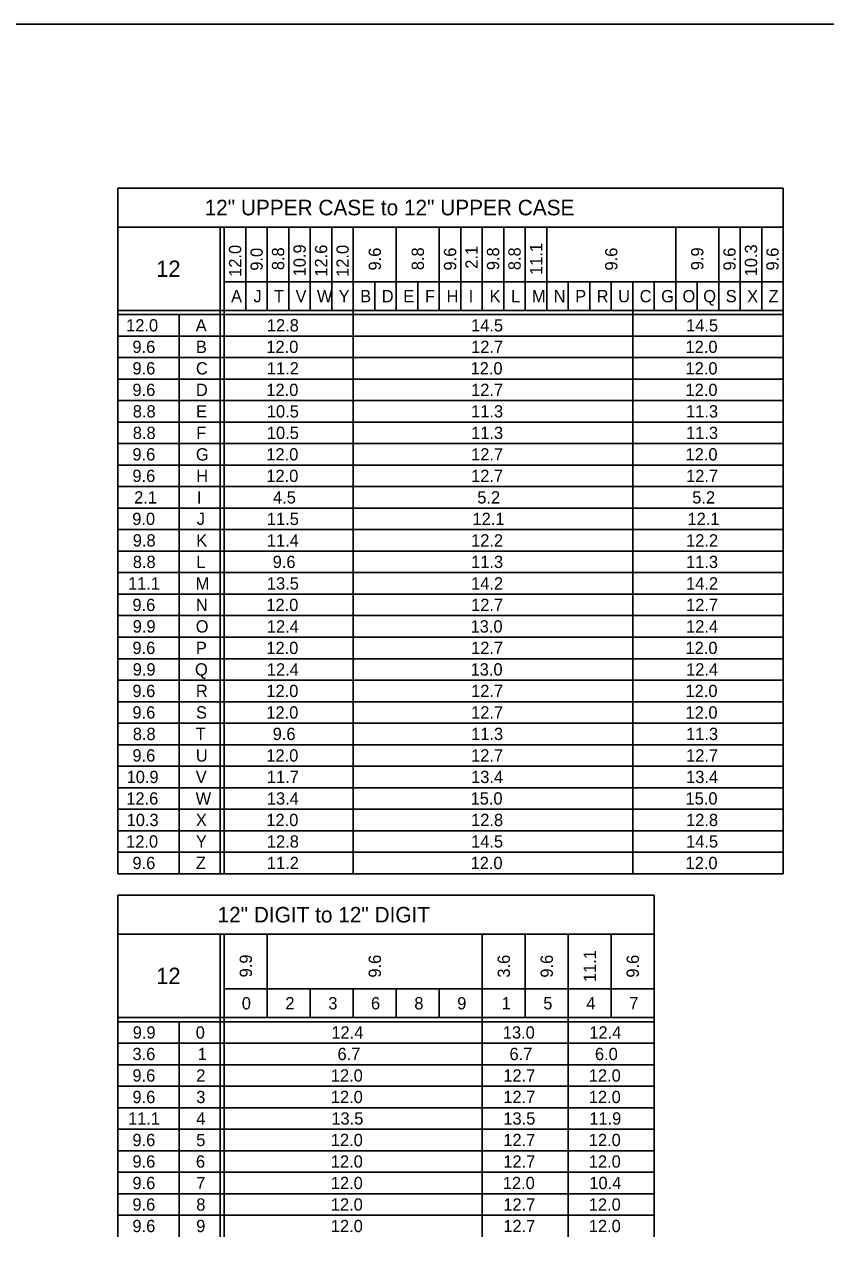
# Model space of a CAD drawing. Extents: x 637580 to 641849, y 297270 to 299646.
# Drawn here: x 640337.3 to 640533.1, y 298740.6 to 299036.6 of the extents above; entities that cross this region are included whole.
import ezdxf

# ---------------------------------------------------------------- set-up
doc = ezdxf.new("R2010")
doc.units = 0
doc.layers.add('1', color=7, linetype='Continuous')
doc.layers.add('2', color=7, linetype='Continuous')

msp = doc.modelspace()

# ---------------------------------------------------------------- linework, layer by layer
at = {"layer": '1'}
msp.add_line((640143.31, 299036.63), (640929.31, 299036.63), dxfattribs=at)
at = {"layer": '2'}
for p, q in [((640522.71, 298996.63), (640360.21, 298996.63)), ((640360.21, 298996.63), (640360.21, 298829.25)), ((640522.71, 298996.63), (640522.71, 298829.25)), ((640360.21, 298987.13), (640522.71, 298987.13)), ((640385.21, 298987.13), (640385.21, 298829.25)), ((640386.21, 298987.13), (640386.21, 298829.25)), ((640391.46, 298987.13), (640391.46, 298966.75)), ((640396.71, 298987.13), (640396.71, 298966.75)), ((640401.96, 298987.13), (640401.96, 298966.75)), ((640407.21, 298987.13), (640407.21, 298966.75)), ((640412.46, 298987.13), (640412.46, 298966.75)), ((640417.71, 298987.13), (640417.71, 298829.25)), ((640428.21, 298987.13), (640428.21, 298966.75)), ((640438.71, 298987.13), (640438.71, 298966.75)), ((640443.96, 298987.13), (640443.96, 298966.75)), ((640449.21, 298987.13), (640449.21, 298966.75)), ((640454.46, 298987.13), (640454.46, 298966.75)), ((640459.71, 298987.13), (640459.71, 298966.75)), ((640464.96, 298987.13), (640464.96, 298966.75)), ((640496.46, 298987.13), (640496.46, 298966.75)), ((640506.96, 298987.13), (640506.96, 298966.75)), ((640512.21, 298987.13), (640512.21, 298966.75)), ((640517.46, 298987.13), (640517.46, 298966.75)), ((640386.21, 298973.75), (640522.71, 298973.75)), ((640422.96, 298973.75), (640422.96, 298966.75)), ((640433.46, 298973.75), (640433.46, 298966.75)), ((640470.21, 298973.75), (640470.21, 298966.75)), ((640475.46, 298973.75), (640475.46, 298966.75)), ((640480.71, 298973.75), (640480.71, 298966.75)), ((640480.71, 298973.75), (640480.71, 298966.75)), ((640485.96, 298973.75), (640485.96, 298829.25)), ((640491.21, 298973.75), (640491.21, 298966.75)), ((640501.71, 298973.75), (640501.71, 298966.75)), ((640522.71, 298966.75), (640360.21, 298966.75)), ((640522.71, 298965.75), (640360.21, 298965.75)), ((640375.21, 298965.75), (640375.21, 298829.25)), ((640522.71, 298960.5), (640360.21, 298960.5)), ((640522.71, 298955.25), (640360.21, 298955.25)), ((640522.71, 298950), (640360.21, 298950)), ((640522.71, 298944.75), (640360.21, 298944.75)), ((640522.71, 298939.5), (640360.21, 298939.5)), ((640522.71, 298934.25), (640360.21, 298934.25)), ((640522.71, 298929), (640360.21, 298929)), ((640522.71, 298923.75), (640360.21, 298923.75)), ((640522.71, 298918.5), (640360.21, 298918.5)), ((640522.71, 298913.25), (640360.21, 298913.25)), ((640522.71, 298908), (640360.21, 298908)), ((640522.71, 298902.75), (640360.21, 298902.75)), ((640522.71, 298897.5), (640360.21, 298897.5)), ((640522.71, 298892.25), (640360.21, 298892.25)), ((640522.71, 298887), (640360.21, 298887)), ((640522.71, 298881.75), (640360.21, 298881.75)), ((640522.71, 298876.5), (640360.21, 298876.5)), ((640522.71, 298871.25), (640360.21, 298871.25)), ((640522.71, 298866), (640360.21, 298866)), ((640522.71, 298860.75), (640360.21, 298860.75)), ((640522.71, 298855.5), (640360.21, 298855.5)), ((640522.71, 298850.25), (640360.21, 298850.25)), ((640522.71, 298845), (640360.21, 298845)), ((640522.71, 298839.75), (640360.21, 298839.75)), ((640522.71, 298834.5), (640360.21, 298834.5)), ((640360.21, 298829.25), (640360.21, 298829.25)), ((640360.21, 298829.25), (640522.71, 298829.25)), ((640491.21, 298824), (640360.21, 298824)), ((640360.21, 298824), (640360.21, 298740.63)), ((640491.21, 298740.63), (640491.21, 298824)), ((640360.21, 298814.5), (640491.21, 298814.5)), ((640385.21, 298814.5), (640385.21, 298740.63)), ((640386.21, 298814.5), (640386.21, 298740.63)), ((640396.71, 298814.5), (640396.71, 298794.13)), ((640449.21, 298814.5), (640449.21, 298740.63)), ((640459.71, 298814.5), (640459.71, 298794.13)), ((640470.21, 298814.5), (640470.21, 298740.63)), ((640480.71, 298814.5), (640480.71, 298794.13)), ((640386.21, 298801.13), (640491.21, 298801.13)), ((640407.21, 298801.13), (640407.21, 298794.13)), ((640417.71, 298801.13), (640417.71, 298794.13)), ((640428.21, 298801.13), (640428.21, 298794.13)), ((640438.71, 298801.13), (640438.71, 298794.13)), ((640491.21, 298794.13), (640360.21, 298794.13)), ((640491.21, 298793.13), (640360.21, 298793.13)), ((640375.21, 298793.13), (640375.21, 298740.63)), ((640491.21, 298787.88), (640360.21, 298787.88)), ((640491.21, 298782.63), (640360.21, 298782.63)), ((640491.21, 298777.38), (640360.21, 298777.38)), ((640491.21, 298772.13), (640360.21, 298772.13)), ((640491.21, 298766.88), (640360.21, 298766.88)), ((640491.21, 298761.63), (640360.21, 298761.63)), ((640491.21, 298756.38), (640360.21, 298756.38)), ((640491.21, 298751.13), (640360.21, 298751.13)), ((640491.21, 298745.88), (640360.21, 298745.88))]:
    msp.add_line(p, q, dxfattribs=at)

# ---------------------------------------------------------------- texts
for s, height, p in [('12" UPPER CASE to 12" UPPER CASE', 3.8, (640381.4, 298989.98)), ('12', 4, (640369.58, 298974.94)), ('A', 3, (640387.86, 298968.75)), ('J', 3, (640393.34, 298968.75)), ('T', 3, (640398.34, 298968.75)), ('V', 3, (640403.61, 298968.75)), ('W', 3, (640408.83, 298968.75)), ('Y', 3, (640414.14, 298968.75)), ('B', 3, (640419.4, 298968.75)), ('D', 3, (640424.65, 298968.75)), ('E', 3, (640429.92, 298968.75)), ('F', 3, (640435.22, 298968.75)), ('H', 3, (640440.49, 298968.75)), ('I', 3, (640445.9, 298968.75)), ('K', 3, (640450.99, 298968.75)), ('L', 3, (640456.24, 298968.75)), ('M', 3, (640461.33, 298968.75)), ('N', 3, (640466.65, 298968.75)), ('P', 3, (640471.9, 298968.75)), ('R', 3, (640477.15, 298968.75)), ('U', 3, (640482.39, 298968.75)), ('C', 3, (640487.65, 298968.75)), ('G', 3, (640492.9, 298968.75)), ('O', 3, (640498.11, 298968.75)), ('Q', 3, (640503.18, 298968.75)), ('S', 3, (640508.67, 298968.75)), ('X', 3, (640513.89, 298968.75)), ('Z', 3, (640519.15, 298968.75)), ('12.0', 3, (640362.23, 298961.63)), ('A', 3, (640379.23, 298961.63)), ('12.8', 3, (640396.61, 298961.63)), ('14.5', 3, (640446.49, 298961.63)), ('14.5', 3, (640498.99, 298961.63)), ('9.6', 3, (640363.78, 298956.38)), ('B', 3, (640379.28, 298956.38)), ('12.0', 3, (640396.48, 298956.38)), ('12.7', 3, (640446.49, 298956.38)), ('12.0', 3, (640498.86, 298956.38)), ('9.6', 3, (640363.78, 298951.13)), ('C', 3, (640379.28, 298951.13)), ('11.2', 3, (640396.61, 298951.13)), ('12.0', 3, (640446.36, 298951.13)), ('12.0', 3, (640498.86, 298951.13)), ('9.6', 3, (640363.78, 298945.88)), ('D', 3, (640379.28, 298945.88)), ('12.0', 3, (640396.48, 298945.88)), ('12.7', 3, (640446.49, 298945.88)), ('12.0', 3, (640498.86, 298945.88)), ('8.8', 3, (640363.86, 298940.63)), ('E', 3, (640379.29, 298940.63)), ('10.5', 3, (640396.61, 298940.63)), ('11.3', 3, (640446.49, 298940.63)), ('11.3', 3, (640498.99, 298940.63)), ('8.8', 3, (640363.86, 298935.38)), ('F', 3, (640379.35, 298935.38)), ('10.5', 3, (640396.61, 298935.38)), ('11.3', 3, (640446.49, 298935.38)), ('11.3', 3, (640498.99, 298935.38)), ('9.6', 3, (640363.78, 298930.13)), ('G', 3, (640379.28, 298930.13)), ('12.0', 3, (640396.48, 298930.13)), ('12.7', 3, (640446.49, 298930.13)), ('12.0', 3, (640498.86, 298930.13)), ('9.6', 3, (640363.78, 298924.88)), ('H', 3, (640379.36, 298924.88)), ('12.0', 3, (640396.48, 298924.88)), ('12.7', 3, (640446.49, 298924.88)), ('12.7', 3, (640498.99, 298924.88)), ('2.1', 3, (640364.2, 298919.63)), ('I', 3, (640379.53, 298919.63)), ('4.5', 3, (640398.11, 298919.63)), ('5.2', 3, (640447.99, 298919.63)), ('5.2', 3, (640500.49, 298919.63)), ('9.0', 3, (640363.73, 298914.38)), ('J', 3, (640379.47, 298914.38)), ('11.5', 3, (640396.61, 298914.38)), ('12.1', 3, (640446.83, 298914.38)), ('12.1', 3, (640499.33, 298914.38)), ('9.8', 3, (640363.86, 298909.13)), ('K', 3, (640379.36, 298909.13)), ('11.4', 3, (640396.61, 298909.13)), ('12.2', 3, (640446.49, 298909.13)), ('12.2', 3, (640498.99, 298909.13)), ('8.8', 3, (640363.86, 298903.88)), ('L', 3, (640379.36, 298903.88)), ('9.6', 3, (640398.03, 298903.88)), ('11.3', 3, (640446.49, 298903.88)), ('11.3', 3, (640498.99, 298903.88)), ('11.1', 3, (640362.7, 298898.63)), ('M', 3, (640379.21, 298898.63)), ('13.5', 3, (640396.61, 298898.63)), ('14.2', 3, (640446.49, 298898.63)), ('14.2', 3, (640498.99, 298898.63)), ('9.6', 3, (640363.78, 298893.38)), ('N', 3, (640379.28, 298893.38)), ('12.0', 3, (640396.48, 298893.38)), ('12.7', 3, (640446.49, 298893.38)), ('12.7', 3, (640498.99, 298893.38)), ('9.9', 3, (640363.85, 298888.13)), ('O', 3, (640379.23, 298888.13)), ('12.4', 3, (640396.61, 298888.13)), ('13.0', 3, (640446.36, 298888.13)), ('12.4', 3, (640498.99, 298888.13)), ('9.6', 3, (640363.78, 298882.88)), ('P', 3, (640379.28, 298882.88)), ('12.0', 3, (640396.48, 298882.88)), ('12.7', 3, (640446.49, 298882.88)), ('12.0', 3, (640498.86, 298882.88)), ('9.9', 3, (640363.85, 298877.63)), ('Q', 3, (640379.05, 298877.63)), ('12.4', 3, (640396.61, 298877.63)), ('13.0', 3, (640446.36, 298877.63)), ('12.4', 3, (640498.99, 298877.63)), ('9.6', 3, (640363.78, 298872.38)), ('R', 3, (640379.28, 298872.38)), ('12.0', 3, (640396.48, 298872.38)), ('12.7', 3, (640446.49, 298872.38)), ('12.0', 3, (640498.86, 298872.38)), ('9.6', 3, (640363.78, 298867.13)), ('S', 3, (640379.29, 298867.13)), ('12.0', 3, (640396.48, 298867.13)), ('12.7', 3, (640446.49, 298867.13)), ('12.0', 3, (640498.86, 298867.13)), ('8.8', 3, (640363.86, 298861.88)), ('T', 3, (640379.22, 298861.88)), ('9.6', 3, (640398.03, 298861.88)), ('11.3', 3, (640446.49, 298861.88)), ('11.3', 3, (640498.99, 298861.88)), ('9.6', 3, (640363.78, 298856.63)), ('U', 3, (640379.27, 298856.63)), ('12.0', 3, (640396.48, 298856.63)), ('12.7', 3, (640446.49, 298856.63)), ('12.7', 3, (640498.99, 298856.63)), ('10.9', 3, (640362.35, 298851.38)), ('V', 3, (640379.23, 298851.38)), ('11.7', 3, (640396.61, 298851.38)), ('13.4', 3, (640446.49, 298851.38)), ('13.4', 3, (640498.99, 298851.38)), ('12.6', 3, (640362.28, 298846.13)), ('W', 3, (640379.21, 298846.13)), ('13.4', 3, (640396.61, 298846.13)), ('15.0', 3, (640446.36, 298846.13)), ('15.0', 3, (640498.86, 298846.13)), ('10.3', 3, (640362.36, 298840.88)), ('X', 3, (640379.27, 298840.88)), ('12.0', 3, (640396.48, 298840.88)), ('12.8', 3, (640446.49, 298840.88)), ('12.8', 3, (640498.99, 298840.88)), ('12.0', 3, (640362.23, 298835.63)), ('12.8', 3, (640396.61, 298835.63)), ('Y', 3, (640379.27, 298835.63)), ('14.5', 3, (640446.49, 298835.63)), ('14.5', 3, (640498.99, 298835.63)), ('9.6', 3, (640363.78, 298830.38)), ('Z', 3, (640379.28, 298830.38)), ('11.2', 3, (640396.61, 298830.38)), ('12.0', 3, (640446.36, 298830.38)), ('12.0', 3, (640498.86, 298830.38)), ('12" DIGIT to 12" DIGIT', 3.8, (640384.56, 298817.35)), ('12', 4, (640369.58, 298802.31)), ('0', 3, (640390.48, 298796.13)), ('2', 3, (640401.11, 298796.13)), ('3', 3, (640411.61, 298796.13)), ('6', 3, (640422.03, 298796.13)), ('8', 3, (640432.61, 298796.13)), ('9', 3, (640443.1, 298796.13)), ('1', 3, (640453.95, 298796.13)), ('5', 3, (640464.11, 298796.13)), ('4', 3, (640474.61, 298796.13)), ('7', 3, (640485.11, 298796.13)), ('9.9', 3, (640363.85, 298789)), ('0', 3, (640379.23, 298789)), ('12.4', 3, (640412.36, 298789)), ('13.0', 3, (640454.23, 298789)), ('12.4', 3, (640475.36, 298789)), ('3.6', 3, (640363.78, 298783.75)), ('1', 3, (640379.7, 298783.75)), ('6.7', 3, (640413.86, 298783.75)), ('6.7', 3, (640455.86, 298783.75)), ('6.0', 3, (640476.73, 298783.75)), ('9.6', 3, (640363.78, 298778.5)), ('2', 3, (640379.36, 298778.5)), ('12.0', 3, (640412.23, 298778.5)), ('12.7', 3, (640454.36, 298778.5)), ('12.0', 3, (640475.23, 298778.5)), ('9.6', 3, (640363.78, 298773.25)), ('3', 3, (640379.36, 298773.25)), ('12.0', 3, (640412.23, 298773.25)), ('12.7', 3, (640454.36, 298773.25)), ('12.0', 3, (640475.23, 298773.25)), ('11.1', 3, (640362.7, 298768)), ('4', 3, (640379.36, 298768)), ('13.5', 3, (640412.36, 298768)), ('13.5', 3, (640454.36, 298768)), ('11.9', 3, (640475.35, 298768)), ('9.6', 3, (640363.78, 298762.75)), ('5', 3, (640379.36, 298762.75)), ('12.0', 3, (640412.23, 298762.75)), ('12.7', 3, (640454.36, 298762.75)), ('12.0', 3, (640475.23, 298762.75)), ('9.6', 3, (640363.78, 298757.5)), ('6', 3, (640379.28, 298757.5)), ('12.0', 3, (640412.23, 298757.5)), ('12.7', 3, (640454.36, 298757.5)), ('12.0', 3, (640475.23, 298757.5)), ('9.6', 3, (640363.78, 298752.25)), ('7', 3, (640379.36, 298752.25)), ('12.0', 3, (640412.23, 298752.25)), ('12.0', 3, (640454.23, 298752.25)), ('10.4', 3, (640475.36, 298752.25)), ('9.6', 3, (640363.78, 298747)), ('8', 3, (640379.36, 298747)), ('12.0', 3, (640412.23, 298747)), ('12.7', 3, (640454.36, 298747)), ('12.0', 3, (640475.23, 298747)), ('9.6', 3, (640363.78, 298741.75)), ('9', 3, (640379.35, 298741.75)), ('12.0', 3, (640412.23, 298741.75)), ('12.7', 3, (640454.36, 298741.75)), ('12.0', 3, (640475.23, 298741.75))]:
    msp.add_text(s, height=height, dxfattribs=at).set_placement(p)
for s, p in [('12.0', (640390.34, 298974.96)), ('9.0', (640395.59, 298976.46)), ('8.8', (640400.84, 298976.59)), ('10.9', (640406.09, 298975.08)), ('12.6', (640411.34, 298975.01)), ('12.0', (640416.59, 298974.96)), ('9.6', (640424.46, 298976.51)), ('8.8', (640434.96, 298976.59)), ('9.6', (640442.84, 298976.51)), ('2.1', (640448.09, 298976.93)), ('9.8', (640453.34, 298976.59)), ('8.8', (640458.59, 298976.59)), ('11.1', (640463.84, 298975.43)), ('9.6', (640482.21, 298976.51)), ('9.9', (640503.21, 298976.58)), ('9.6', (640511.09, 298976.51)), ('10.3', (640516.34, 298975.09)), ('9.6', (640521.59, 298976.51)), ('9.9', (640392.96, 298803.95)), ('9.6', (640424.46, 298803.88)), ('3.6', (640455.96, 298803.88)), ('9.6', (640466.46, 298803.88)), ('11.1', (640476.96, 298802.81)), ('9.6', (640487.46, 298803.88))]:
    msp.add_text(s, height=3, rotation=90, dxfattribs=at).set_placement(p)

doc.saveas('drawing.dxf')
